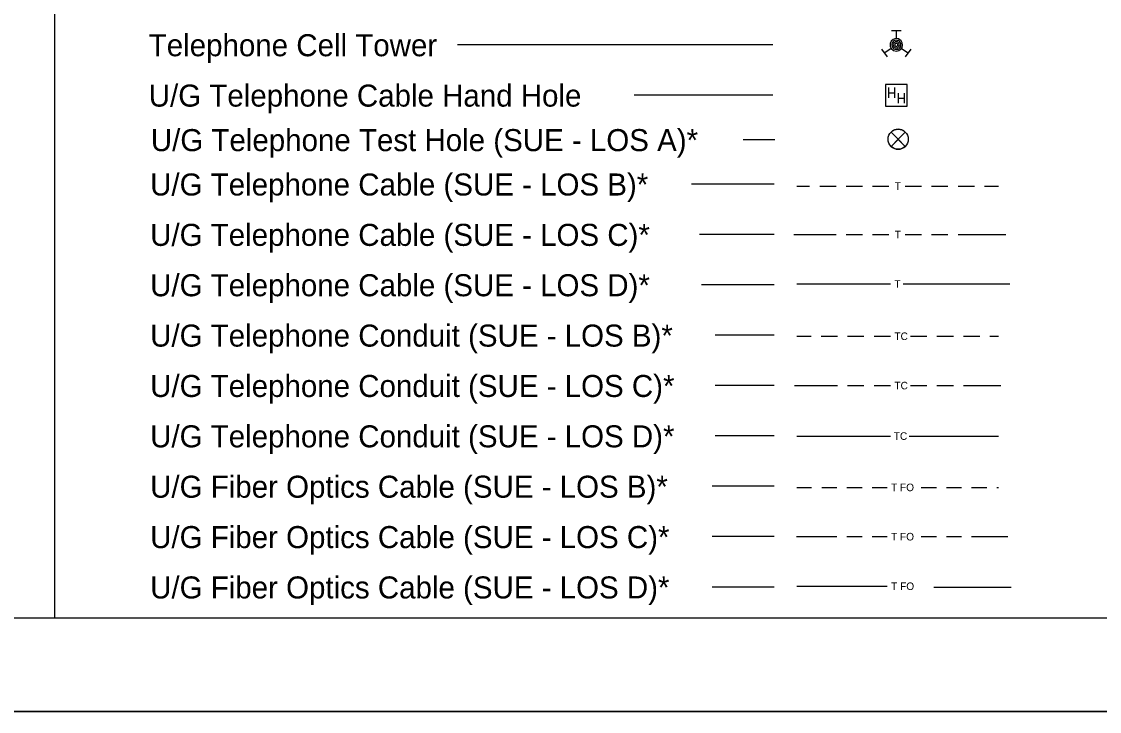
# Model space of a CAD drawing. Extents: x 754056.72 to 754059.56, y 596603.78 to 596605.61.
# Drawn here: x 754058.119 to 754058.839, y 596603.778 to 596604.239 of the extents above; entities that cross this region are included whole.
import ezdxf

# ---------------------------------------------------------------- set-up
doc = ezdxf.new("R2010")
doc.units = 0
for name, color, linetype in [('Exist Utilities Telephone Test Hole SUE LOS A CELL', 7, 'Continuous'), ('Sheet_Plan', 7, 'Continuous'), ('Sheet_Plot_Border_Outside_CELL', 7, 'Continuous'), ('Sheet_Symbology', 7, 'Continuous'), ('z - Construction', 7, 'Continuous')]:
    doc.layers.add(name, color=color, linetype=linetype)

msp = doc.modelspace()

# ---------------------------------------------------------------- linework, layer by layer
at = {"layer": 'Exist Utilities Telephone Test Hole SUE LOS A CELL'}
for points in [[(754058.7092, 596604.16509), (754058.69969, 596604.15558), (754058.70445, 596604.16033), (754058.69969, 596604.16509), (754058.7092, 596604.15558)], [(754058.69969, 596604.16509), (754058.70445, 596604.16033), (754058.7092, 596604.16509)], [(754058.7092, 596604.15558), (754058.70445, 596604.16033), (754058.69969, 596604.15558)]]:
    msp.add_lwpolyline(points, dxfattribs=at)
msp.add_circle((754058.70445, 596604.16033), 0.00672, dxfattribs=at)
for start, end in [(45, 135), (225, 315)]:
    msp.add_arc((754058.70445, 596604.16033), 0.00672, start, end, dxfattribs=at)
at = {"layer": 'Sheet_Plan'}
msp.add_line((754056.78734, 596603.84076), (754059.49562, 596603.84076), dxfattribs=at)
at = {"layer": 'Sheet_Plot_Border_Outside_CELL'}
msp.add_lwpolyline([(754056.72484, 596605.61159), (754059.55817, 596605.61159), (754059.55817, 596603.77826), (754056.72484, 596603.77826)], close=True, dxfattribs=at)
at = {"layer": 'Sheet_Symbology'}
for p, q in [((754058.70008, 596604.23289), (754058.70638, 596604.23289)), ((754058.70323, 596604.22751), (754058.70323, 596604.23289)), ((754058.62081, 596604.22337), (754058.41024, 596604.22337)), ((754058.69725, 596604.21533), (754058.69364, 596604.2205)), ((754058.69985, 596604.22101), (754058.69545, 596604.21792)), ((754058.70662, 596604.22101), (754058.71103, 596604.21792)), ((754058.71284, 596604.22051), (754058.70922, 596604.21534)), ((754058.69808, 596604.19483), (754058.69808, 596604.18805)), ((754058.70195, 596604.19483), (754058.70195, 596604.18805)), ((754058.62081, 596604.18974), (754058.52826, 596604.18974)), ((754058.69808, 596604.19137), (754058.70195, 596604.19137)), ((754058.70454, 596604.19114), (754058.70454, 596604.18436)), ((754058.70454, 596604.18768), (754058.70842, 596604.18768)), ((754058.70842, 596604.19114), (754058.70842, 596604.18436)), ((754058.62219, 596604.16001), (754058.60091, 596604.16001)), ((754058.62173, 596604.13038), (754058.56661, 596604.13038)), ((754058.63689, 596604.12904), (754058.64534, 596604.12904)), ((754058.65206, 596604.12904), (754058.66299, 596604.12904)), ((754058.66972, 596604.12904), (754058.68065, 596604.12904)), ((754058.68738, 596604.12904), (754058.69831, 596604.12904)), ((754058.70907, 596604.12904), (754058.72, 596604.12904)), ((754058.72672, 596604.12904), (754058.73765, 596604.12904)), ((754058.74438, 596604.12904), (754058.75531, 596604.12904)), ((754058.76204, 596604.12904), (754058.77141, 596604.12904)), ((754058.62173, 596604.09675), (754058.57192, 596604.09675)), ((754058.63478, 596604.09675), (754058.66299, 596604.09675)), ((754058.66972, 596604.09675), (754058.68065, 596604.09675)), ((754058.68738, 596604.09675), (754058.69831, 596604.09675)), ((754058.70907, 596604.09675), (754058.72, 596604.09675)), ((754058.72672, 596604.09675), (754058.73765, 596604.09675)), ((754058.74438, 596604.09675), (754058.7764, 596604.09675)), ((754058.62173, 596604.06312), (754058.57321, 596604.06312)), ((754058.63689, 596604.06371), (754058.69931, 596604.06371)), ((754058.70772, 596604.06371), (754058.77899, 596604.06371)), ((754058.62173, 596604.02949), (754058.58228, 596604.02949)), ((754058.63689, 596604.02877), (754058.64628, 596604.02877)), ((754058.65301, 596604.02877), (754058.66394, 596604.02877)), ((754058.67067, 596604.02877), (754058.6816, 596604.02877)), ((754058.68832, 596604.02877), (754058.69925, 596604.02877)), ((754058.7127, 596604.02877), (754058.72363, 596604.02877)), ((754058.73036, 596604.02877), (754058.74129, 596604.02877)), ((754058.74802, 596604.02877), (754058.75895, 596604.02877)), ((754058.76567, 596604.02877), (754058.77141, 596604.02877)), ((754058.62173, 596603.99586), (754058.58228, 596603.99586)), ((754058.63529, 596603.99586), (754058.66394, 596603.99586)), ((754058.67067, 596603.99586), (754058.6816, 596603.99586)), ((754058.68832, 596603.99586), (754058.69925, 596603.99586)), ((754058.7127, 596603.99586), (754058.72363, 596603.99586)), ((754058.73036, 596603.99586), (754058.74129, 596603.99586)), ((754058.74802, 596603.99586), (754058.77302, 596603.99586)), ((754058.62173, 596603.96223), (754058.58228, 596603.96223)), ((754058.63689, 596603.96215), (754058.69925, 596603.96215)), ((754058.71186, 596603.96215), (754058.77141, 596603.96215)), ((754058.62173, 596603.9286), (754058.58032, 596603.9286)), ((754058.63689, 596603.92786), (754058.6467, 596603.92786)), ((754058.65343, 596603.92786), (754058.66352, 596603.92786)), ((754058.67024, 596603.92786), (754058.68033, 596603.92786)), ((754058.68706, 596603.92786), (754058.69715, 596603.92786)), ((754058.71985, 596603.92786), (754058.72994, 596603.92786)), ((754058.73667, 596603.92786), (754058.74676, 596603.92786)), ((754058.75348, 596603.92786), (754058.76357, 596603.92786)), ((754058.7703, 596603.92786), (754058.77141, 596603.92786)), ((754058.62173, 596603.89497), (754058.58032, 596603.89497)), ((754058.63658, 596603.89497), (754058.66352, 596603.89497)), ((754058.67024, 596603.89497), (754058.68033, 596603.89497)), ((754058.68706, 596603.89497), (754058.69715, 596603.89497)), ((754058.71985, 596603.89497), (754058.72994, 596603.89497)), ((754058.73667, 596603.89497), (754058.74676, 596603.89497)), ((754058.75348, 596603.89497), (754058.77755, 596603.89497)), ((754058.62173, 596603.86133), (754058.58032, 596603.86133)), ((754058.63689, 596603.86189), (754058.69721, 596603.86189)), ((754058.72832, 596603.86124), (754058.77982, 596603.86124))]:
    msp.add_line(p, q, dxfattribs=at)
msp.add_lwpolyline([(754058.70323, 596604.21923), (754058.70497, 596604.21956), (754058.70613, 596604.22039), (754058.70704, 596604.22155), (754058.70737, 596604.22312), (754058.7072, 596604.22461), (754058.70638, 596604.2261), (754058.70472, 596604.22734), (754058.70282, 596604.22751), (754058.70116, 596604.22701), (754058.69984, 596604.22585), (754058.69918, 596604.22428), (754058.69918, 596604.22246), (754058.69984, 596604.22089), (754058.70133, 596604.21965)], close=True, dxfattribs=at)
for points in [[(754058.70629, 596604.22337), (754058.70621, 596604.22412), (754058.70596, 596604.22478), (754058.70555, 596604.22536), (754058.70505, 596604.22585), (754058.70447, 596604.22619), (754058.70373, 596604.22635), (754058.70306, 596604.22643), (754058.70232, 596604.22627), (754058.70166, 596604.22602), (754058.70116, 596604.22561), (754058.70067, 596604.22503), (754058.70033, 596604.22445), (754058.70017, 596604.2237), (754058.70017, 596604.22304), (754058.70033, 596604.2223), (754058.70067, 596604.22172), (754058.70116, 596604.22114), (754058.70166, 596604.22072), (754058.70232, 596604.22047), (754058.70306, 596604.22031), (754058.70373, 596604.22039), (754058.70447, 596604.22056), (754058.70505, 596604.22089), (754058.70555, 596604.22139), (754058.70596, 596604.22197), (754058.70621, 596604.22263), (754058.70629, 596604.22337)], [(754058.7053, 596604.22337), (754058.70522, 596604.22395), (754058.70497, 596604.22453), (754058.70455, 596604.22494), (754058.70406, 596604.22528), (754058.70356, 596604.22544), (754058.7029, 596604.22544), (754058.7024, 596604.22528), (754058.70191, 596604.22494), (754058.70149, 596604.22453), (754058.70124, 596604.22395), (754058.70116, 596604.22337), (754058.70124, 596604.22279), (754058.70149, 596604.22221), (754058.70191, 596604.2218), (754058.7024, 596604.22147), (754058.7029, 596604.2213), (754058.70356, 596604.2213), (754058.70406, 596604.22147), (754058.70455, 596604.2218), (754058.70497, 596604.22221), (754058.70522, 596604.22279), (754058.7053, 596604.22337)], [(754058.70422, 596604.22337), (754058.70414, 596604.22378), (754058.70389, 596604.22412), (754058.70356, 596604.22428), (754058.70315, 596604.22436), (754058.70274, 596604.2242), (754058.7024, 596604.22395), (754058.70224, 596604.22354), (754058.70224, 596604.2232), (754058.7024, 596604.22279), (754058.70274, 596604.22254), (754058.70315, 596604.22238), (754058.70356, 596604.22246), (754058.70389, 596604.22263), (754058.70414, 596604.22296), (754058.70422, 596604.22337)], [(754058.69599, 596604.1825), (754058.71047, 596604.1825), (754058.71047, 596604.19698), (754058.69599, 596604.19698), (754058.69599, 596604.1825)]]:
    msp.add_lwpolyline(points, dxfattribs=at)
at = {"layer": 'z - Construction'}
for p, q in [((754058.1415, 596605.54909), (754058.14146, 596603.84076)), ((754056.72484, 596603.77826), (754059.55817, 596603.77826))]:
    msp.add_line(p, q, dxfattribs=at)

# ---------------------------------------------------------------- texts
at = {"layer": 'Sheet_Symbology'}
for s, height, p in [('Telephone Cell Tower', 0.0147137, (754058.20429, 596604.21574)), ('U/G Telephone Cable Hand Hole', 0.0147137, (754058.20429, 596604.18211)), ('U/G Telephone Test Hole (SUE - LOS A)*', 0.0147137, (754058.20567, 596604.15238)), ('U/G Telephone Cable (SUE - LOS B)*', 0.0147137, (754058.20521, 596604.12275)), ('T', 0.00504, (754058.70209, 596604.12652)), ('U/G Telephone Cable (SUE - LOS C)*', 0.0147137, (754058.20521, 596604.08912)), ('T', 0.00504, (754058.70209, 596604.09423)), ('U/G Telephone Cable (SUE - LOS D)*', 0.0147137, (754058.20521, 596604.05549)), ('T', 0.00504, (754058.70192, 596604.06119)), ('U/G Telephone Conduit (SUE - LOS B)*', 0.0147137, (754058.20521, 596604.02186)), ('TC', 0.005045, (754058.70194, 596604.02625)), ('U/G Telephone Conduit (SUE - LOS C)*', 0.0147137, (754058.20521, 596603.98823)), ('TC', 0.005045, (754058.70194, 596603.99334)), ('U/G Telephone Conduit (SUE - LOS D)*', 0.0147137, (754058.20521, 596603.9546)), ('TC', 0.005045, (754058.70152, 596603.95962)), ('U/G Fiber Optics Cable (SUE - LOS B)*', 0.0147137, (754058.20521, 596603.92097)), ('T FO', 0.005045, (754058.69967, 596603.92534)), ('U/G Fiber Optics Cable (SUE - LOS C)*', 0.0147137, (754058.20521, 596603.88733)), ('T FO', 0.005045, (754058.69967, 596603.89244)), ('U/G Fiber Optics Cable (SUE - LOS D)*', 0.0147137, (754058.20521, 596603.8537)), ('T FO', 0.005045, (754058.69974, 596603.85936))]:
    msp.add_text(s, height=height, dxfattribs=at).set_placement(p)

doc.saveas('drawing.dxf')
